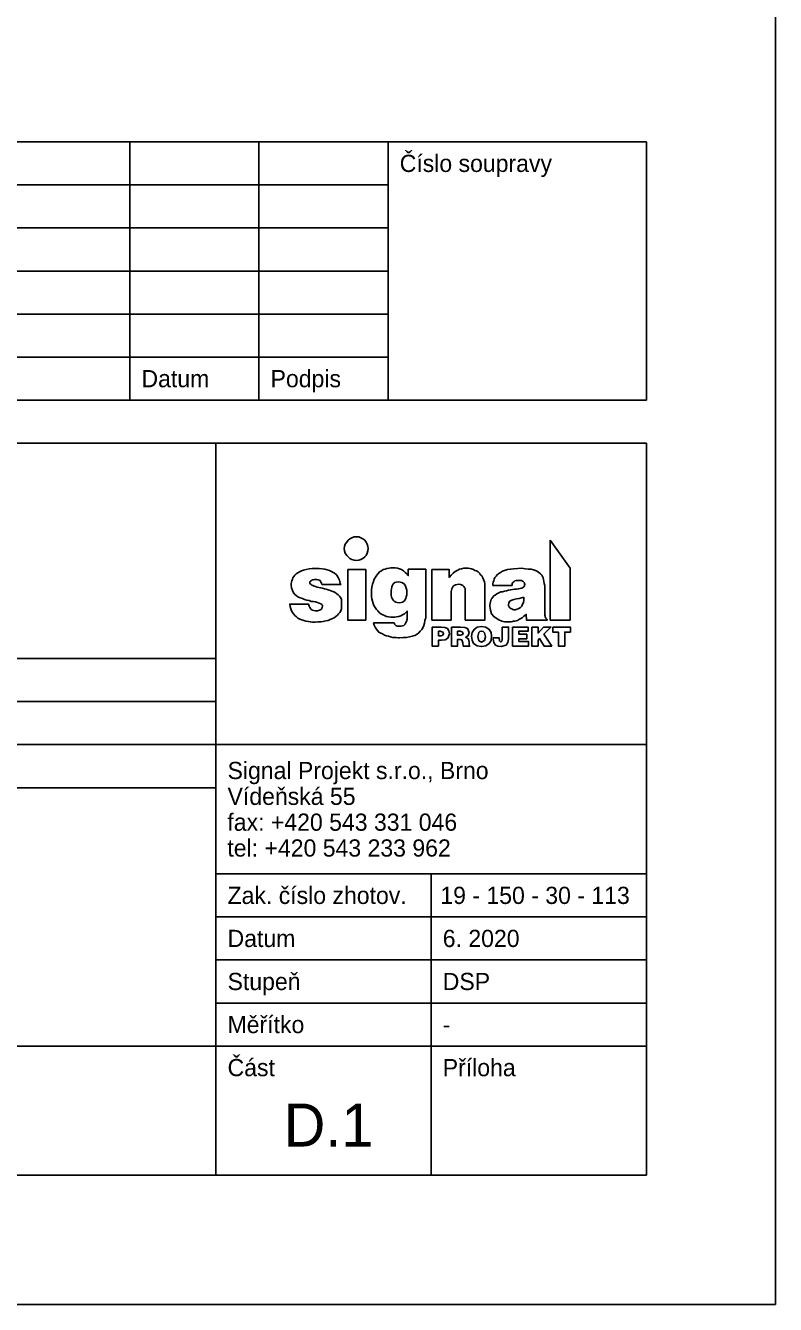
# Model space of a CAD drawing. Extents: x -790471 to -790261, y -986448 to -986151.
# Drawn here: x -790347.7 to -790260.6, y -986447.6 to -986299.1 of the extents above; entities that cross this region are included whole.
import ezdxf

# ---------------------------------------------------------------- set-up
doc = ezdxf.new("R2010")
doc.units = 0
for name, color, linetype in [('Info o rozpiskách', 7, 'Continuous'), ('popis', 7, 'Continuous'), ('Ramečky', 7, 'Continuous'), ('Rámečky-tisk', 7, 'Continuous'), ('Text', 7, 'Continuous'), ('Text barevný', 7, 'Continuous')]:
    doc.layers.add(name, color=color, linetype=linetype)

msp = doc.modelspace()

# ---------------------------------------------------------------- linework, layer by layer
at = {"layer": 'Info o rozpiskách'}
for points in [[(-790309.25, -986358.46), (-790308.98, -986358.47), (-790308.76, -986358.57), (-790308.54, -986358.7), (-790308.29, -986358.87), (-790308.15, -986359.07), (-790308.03, -986359.31), (-790307.94, -986359.58), (-790307.92, -986359.84), (-790307.94, -986360.1), (-790308.03, -986360.38), (-790308.15, -986360.62), (-790308.29, -986360.79), (-790308.54, -986360.99), (-790308.76, -986361.09), (-790308.98, -986361.18), (-790309.25, -986361.2), (-790309.54, -986361.18), (-790309.79, -986361.09), (-790310.05, -986360.99), (-790310.23, -986360.79), (-790310.4, -986360.62), (-790310.57, -986360.38), (-790310.65, -986360.1), (-790310.7, -986359.84), (-790310.65, -986359.58), (-790310.57, -986359.31), (-790310.4, -986359.07), (-790310.23, -986358.87), (-790310.05, -986358.7), (-790309.79, -986358.57), (-790309.54, -986358.47), (-790309.25, -986358.46)], [(-790300.48, -986368.94), (-790299.41, -986368.94), (-790299, -986368.98), (-790298.7, -986369.13), (-790298.52, -986369.37), (-790298.46, -986369.72), (-790298.65, -986370.25), (-790298.95, -986370.42), (-790299.38, -986370.47), (-790299.75, -986370.47), (-790299.75, -986371.16), (-790300.48, -986371.16), (-790300.48, -986368.94)], [(-790299.75, -986369.44), (-790299.75, -986369.95), (-790299.43, -986369.95), (-790299.25, -986369.89), (-790299.15, -986369.69), (-790299.23, -986369.52), (-790299.54, -986369.44), (-790299.75, -986369.44)], [(-790298.24, -986368.94), (-790297.16, -986368.94), (-790296.67, -986368.98), (-790296.35, -986369.13), (-790296.19, -986369.58), (-790296.3, -986369.93), (-790296.56, -986370.12), (-790296.24, -986370.34), (-790296.19, -986370.71), (-790296.19, -986370.88), (-790296.17, -986371.05), (-790296.11, -986371.11), (-790296.11, -986371.16), (-790296.86, -986371.16), (-790296.9, -986370.77), (-790297.03, -986370.42), (-790297.18, -986370.4), (-790297.4, -986370.38), (-790297.51, -986370.38), (-790297.51, -986371.16), (-790298.24, -986371.16), (-790298.24, -986368.94)], [(-790297.51, -986369.44), (-790297.51, -986369.89), (-790297.19, -986369.89), (-790296.93, -986369.82), (-790296.88, -986369.69), (-790296.95, -986369.52), (-790297.16, -986369.44), (-790297.51, -986369.44)], [(-790294.73, -986368.89), (-790294.23, -986368.96), (-790293.84, -986369.22), (-790293.63, -986369.59), (-790293.56, -986370.02), (-790293.63, -986370.49), (-790293.85, -986370.86), (-790294.23, -986371.12), (-790294.73, -986371.22), (-790295.25, -986371.12), (-790295.65, -986370.84), (-790295.83, -986370.47), (-790295.91, -986370.02), (-790295.83, -986369.58), (-790295.61, -986369.22), (-790295.23, -986368.96), (-790294.73, -986368.89)], [(-790294.73, -986369.43), (-790294.92, -986369.46), (-790295.05, -986369.58), (-790295.16, -986370.04), (-790295.05, -986370.53), (-790294.73, -986370.68), (-790294.38, -986370.49), (-790294.28, -986370.08), (-790294.4, -986369.61), (-790294.53, -986369.46), (-790294.73, -986369.43)], [(-790292.33, -986368.94), (-790291.6, -986368.94), (-790291.6, -986370.32), (-790291.67, -986370.75), (-790291.88, -986371.05), (-790292.46, -986371.22), (-790292.83, -986371.18), (-790293.11, -986371.03), (-790293.29, -986370.75), (-790293.37, -986370.36), (-790293.35, -986370.19), (-790292.7, -986370.19), (-790292.66, -986370.56), (-790292.51, -986370.68), (-790292.38, -986370.6), (-790292.33, -986370.42), (-790292.33, -986368.94)], [(-790291.13, -986368.94), (-790289.32, -986368.94), (-790289.32, -986369.44), (-790290.4, -986369.44), (-790290.4, -986369.78), (-790289.49, -986369.78), (-790289.49, -986370.3), (-790290.4, -986370.3), (-790290.4, -986370.64), (-790289.27, -986370.64), (-790289.27, -986371.16), (-790291.13, -986371.16), (-790291.13, -986368.94)], [(-790288.91, -986368.94), (-790288.16, -986368.94), (-790288.16, -986369.65), (-790287.53, -986368.94), (-790286.67, -986368.94), (-790287.49, -986369.78), (-790286.58, -986371.16), (-790287.46, -986371.16), (-790288, -986370.28), (-790288.16, -986370.45), (-790288.16, -986371.16), (-790288.91, -986371.16), (-790288.91, -986368.94)], [(-790286.47, -986368.94), (-790284.41, -986368.94), (-790284.41, -986369.52), (-790285.07, -986369.52), (-790285.07, -986371.16), (-790285.8, -986371.16), (-790285.8, -986369.52), (-790286.47, -986369.52), (-790286.47, -986368.94)]]:
    msp.add_lwpolyline(points, dxfattribs=at)
at = {"layer": 'popis'}
for points in [[(-790286.77, -986358.87), (-790286.77, -986368.14), (-790284.45, -986368.14), (-790284.45, -986362.11), (-790286.77, -986358.87)], [(-790313.29, -986364.02), (-790311.09, -986364.02), (-790311.15, -986363.83), (-790311.19, -986363.66), (-790311.24, -986363.49), (-790311.32, -986363.33), (-790311.41, -986363.18), (-790311.52, -986363.01), (-790311.63, -986362.86), (-790311.8, -986362.69), (-790311.97, -986362.6), (-790312.17, -986362.49), (-790312.4, -986362.39), (-790312.66, -986362.3), (-790312.94, -986362.24), (-790313.26, -986362.19), (-790313.61, -986362.15), (-790314, -986362.13), (-790314.4, -986362.15), (-790314.77, -986362.19), (-790315.09, -986362.26), (-790315.4, -986362.32), (-790315.66, -986362.41), (-790315.89, -986362.52), (-790316.07, -986362.65), (-790316.26, -986362.78), (-790316.43, -986362.93), (-790316.54, -986363.08), (-790316.65, -986363.23), (-790316.71, -986363.4), (-790316.78, -986363.59), (-790316.82, -986363.75), (-790316.86, -986363.89), (-790316.86, -986364.09), (-790316.8, -986364.39), (-790316.71, -986364.69), (-790316.62, -986364.91), (-790316.43, -986365.15), (-790316.26, -986365.28), (-790316.06, -986365.45), (-790315.81, -986365.56), (-790315.55, -986365.64), (-790315.29, -986365.73), (-790315.03, -986365.81), (-790314.77, -986365.88), (-790314.51, -986365.96), (-790314.25, -986365.99), (-790314.02, -986366.03), (-790313.8, -986366.09), (-790313.59, -986366.18), (-790313.39, -986366.25), (-790313.29, -986366.33), (-790313.22, -986366.42), (-790313.2, -986366.52), (-790313.24, -986366.68), (-790313.29, -986366.76), (-790313.33, -986366.85), (-790313.44, -986366.93), (-790313.57, -986367), (-790313.67, -986367.04), (-790313.8, -986367.08), (-790313.93, -986367.08), (-790314.06, -986367.08), (-790314.21, -986367.04), (-790314.38, -986366.98), (-790314.47, -986366.93), (-790314.6, -986366.8), (-790314.69, -986366.68), (-790314.77, -986366.5), (-790314.82, -986366.27), (-790317.01, -986366.27), (-790316.97, -986366.57), (-790316.9, -986366.83), (-790316.8, -986367.06), (-790316.69, -986367.24), (-790316.56, -986367.43), (-790316.41, -986367.6), (-790316.24, -986367.77), (-790316.06, -986367.9), (-790315.83, -986368.01), (-790315.61, -986368.12), (-790315.38, -986368.2), (-790315.14, -986368.27), (-790314.86, -986368.29), (-790314.62, -986368.34), (-790314.38, -986368.36), (-790314.06, -986368.36), (-790313.74, -986368.34), (-790313.43, -986368.34), (-790313.13, -986368.29), (-790312.83, -986368.23), (-790312.55, -986368.18), (-790312.31, -986368.08), (-790312.06, -986367.95), (-790311.86, -986367.86), (-790311.65, -986367.73), (-790311.47, -986367.56), (-790311.34, -986367.41), (-790311.2, -986367.24), (-790311.09, -986367.06), (-790311.02, -986366.83), (-790311, -986366.61), (-790311, -986366.39), (-790311, -986366.33), (-790311, -986366.27), (-790311, -986366.22), (-790311, -986366.16), (-790311, -986366.09), (-790311, -986366.03), (-790311, -986365.99), (-790311, -986365.96), (-790311.02, -986365.71), (-790311.11, -986365.53), (-790311.24, -986365.34), (-790311.39, -986365.21), (-790311.54, -986365.08), (-790311.73, -986364.93), (-790311.9, -986364.84), (-790312.12, -986364.76), (-790312.32, -986364.69), (-790312.55, -986364.61), (-790312.77, -986364.54), (-790312.98, -986364.5), (-790313.22, -986364.44), (-790313.43, -986364.39), (-790313.65, -986364.35), (-790313.84, -986364.3), (-790314.02, -986364.22), (-790314.19, -986364.18), (-790314.32, -986364.11), (-790314.45, -986364.07), (-790314.53, -986364.02), (-790314.64, -986363.94), (-790314.67, -986363.89), (-790314.67, -986363.81), (-790314.67, -986363.74), (-790314.64, -986363.66), (-790314.56, -986363.59), (-790314.49, -986363.55), (-790314.41, -986363.47), (-790314.28, -986363.47), (-790314.13, -986363.44), (-790314, -986363.44), (-790313.85, -986363.44), (-790313.72, -986363.47), (-790313.61, -986363.49), (-790313.5, -986363.55), (-790313.43, -986363.64), (-790313.39, -986363.74), (-790313.31, -986363.85), (-790313.29, -986364.02)], [(-790303.24, -986362.24), (-790303.24, -986362.97), (-790303.41, -986362.77), (-790303.59, -986362.6), (-790303.8, -986362.43), (-790304.04, -986362.28), (-790304.28, -986362.17), (-790304.51, -986362.11), (-790304.75, -986362.08), (-790305.03, -986362.06), (-790305.29, -986362.08), (-790305.48, -986362.09), (-790305.74, -986362.13), (-790305.93, -986362.23), (-790306.15, -986362.28), (-790306.35, -986362.43), (-790306.58, -986362.54), (-790306.76, -986362.73), (-790306.91, -986362.92), (-790307.06, -986363.16), (-790307.19, -986363.4), (-790307.29, -986363.64), (-790307.4, -986363.96), (-790307.47, -986364.3), (-790307.51, -986364.67), (-790307.51, -986365.06), (-790307.51, -986365.38), (-790307.47, -986365.66), (-790307.4, -986365.92), (-790307.32, -986366.2), (-790307.23, -986366.44), (-790307.1, -986366.68), (-790306.93, -986366.89), (-790306.78, -986367.08), (-790306.62, -986367.24), (-790306.45, -986367.39), (-790306.22, -986367.52), (-790306, -986367.62), (-790305.78, -986367.71), (-790305.53, -986367.77), (-790305.29, -986367.8), (-790305.03, -986367.8), (-790304.81, -986367.8), (-790304.6, -986367.77), (-790304.34, -986367.73), (-790304.12, -986367.64), (-790303.91, -986367.54), (-790303.7, -986367.41), (-790303.56, -986367.28), (-790303.39, -986367.09), (-790303.39, -986367.64), (-790303.39, -986368.03), (-790303.46, -986368.29), (-790303.56, -986368.49), (-790303.63, -986368.64), (-790303.76, -986368.75), (-790303.91, -986368.79), (-790304.08, -986368.85), (-790304.26, -986368.85), (-790304.36, -986368.85), (-790304.49, -986368.83), (-790304.6, -986368.79), (-790304.69, -986368.75), (-790304.75, -986368.68), (-790304.84, -986368.61), (-790304.86, -986368.53), (-790304.9, -986368.44), (-790307.27, -986368.44), (-790307.21, -986368.74), (-790307.1, -986368.94), (-790306.97, -986369.17), (-790306.84, -986369.33), (-790306.67, -986369.54), (-790306.45, -986369.65), (-790306.24, -986369.74), (-790306, -986369.89), (-790305.78, -986369.97), (-790305.53, -986370.02), (-790305.31, -986370.08), (-790305.05, -986370.14), (-790304.84, -986370.15), (-790304.66, -986370.17), (-790304.43, -986370.19), (-790304.26, -986370.19), (-790303.85, -986370.17), (-790303.46, -986370.14), (-790303.09, -986370.08), (-790302.79, -986370.01), (-790302.49, -986369.91), (-790302.23, -986369.78), (-790302.03, -986369.63), (-790301.86, -986369.44), (-790301.69, -986369.24), (-790301.56, -986369.02), (-790301.45, -986368.77), (-790301.35, -986368.49), (-790301.32, -986368.2), (-790301.22, -986367.86), (-790301.22, -986367.51), (-790301.22, -986367.09), (-790301.22, -986362.24), (-790303.24, -986362.24)], [(-790300.5, -986362.26), (-790300.5, -986368.14), (-790298.26, -986368.14), (-790298.26, -986365.14), (-790298.26, -986364.82), (-790298.2, -986364.52), (-790298.11, -986364.35), (-790298.03, -986364.2), (-790297.9, -986364.11), (-790297.75, -986364.03), (-790297.57, -986364.02), (-790297.38, -986363.98), (-790297.19, -986364.02), (-790297.06, -986364.05), (-790296.9, -986364.11), (-790296.8, -986364.22), (-790296.73, -986364.35), (-790296.65, -986364.52), (-790296.62, -986364.78), (-790296.62, -986365.04), (-790296.62, -986368.14), (-790294.34, -986368.14), (-790294.34, -986364.59), (-790294.34, -986364.28), (-790294.36, -986363.98), (-790294.41, -986363.7), (-790294.51, -986363.44), (-790294.6, -986363.21), (-790294.71, -986363.01), (-790294.88, -986362.84), (-790294.99, -986362.67), (-790295.14, -986362.54), (-790295.31, -986362.41), (-790295.5, -986362.36), (-790295.68, -986362.26), (-790295.91, -986362.19), (-790296.09, -986362.15), (-790296.28, -986362.11), (-790296.5, -986362.11), (-790296.78, -986362.11), (-790297.06, -986362.19), (-790297.31, -986362.23), (-790297.57, -986362.36), (-790297.81, -986362.49), (-790298.05, -986362.67), (-790298.26, -986362.92), (-790298.5, -986363.18), (-790298.5, -986362.26), (-790300.5, -986362.26)], [(-790293.41, -986364.11), (-790291.19, -986364.11), (-790291.17, -986363.94), (-790291.13, -986363.81), (-790291.06, -986363.72), (-790290.96, -986363.64), (-790290.85, -986363.57), (-790290.7, -986363.53), (-790290.57, -986363.53), (-790290.42, -986363.53), (-790290.25, -986363.53), (-790290.09, -986363.55), (-790289.96, -986363.62), (-790289.88, -986363.66), (-790289.81, -986363.74), (-790289.73, -986363.81), (-790289.73, -986363.9), (-790289.69, -986364), (-790289.73, -986364.09), (-790289.75, -986364.2), (-790289.84, -986364.28), (-790289.94, -986364.35), (-790290.07, -986364.43), (-790290.25, -986364.46), (-790290.46, -986364.5), (-790290.66, -986364.54), (-790290.89, -986364.56), (-790291.13, -986364.59), (-790291.36, -986364.63), (-790291.6, -986364.67), (-790291.84, -986364.73), (-790292.08, -986364.76), (-790292.29, -986364.84), (-790292.51, -986364.87), (-790292.74, -986364.97), (-790292.96, -986365.08), (-790293.15, -986365.23), (-790293.31, -986365.32), (-790293.44, -986365.47), (-790293.54, -986365.62), (-790293.61, -986365.71), (-790293.67, -986365.88), (-790293.7, -986366.03), (-790293.74, -986366.2), (-790293.76, -986366.35), (-790293.76, -986366.52), (-790293.7, -986367), (-790293.56, -986367.39), (-790293.31, -986367.73), (-790293.05, -986367.93), (-790292.74, -986368.12), (-790292.38, -986368.25), (-790292.06, -986368.33), (-790291.73, -986368.34), (-790291.58, -986368.34), (-790291.45, -986368.33), (-790291.3, -986368.33), (-790291.13, -986368.29), (-790291.02, -986368.27), (-790290.85, -986368.25), (-790290.7, -986368.21), (-790290.57, -986368.18), (-790290.44, -986368.1), (-790290.31, -986368.03), (-790290.18, -986367.97), (-790290.03, -986367.88), (-790289.92, -986367.78), (-790289.81, -986367.67), (-790289.66, -986367.56), (-790289.55, -986367.47), (-790289.51, -986368.16), (-790287.12, -986368.16), (-790287.12, -986368.06), (-790287.25, -986367.93), (-790287.31, -986367.84), (-790287.36, -986367.75), (-790287.36, -986367.67), (-790287.4, -986367.56), (-790287.4, -986367.49), (-790287.4, -986367.37), (-790287.4, -986367.23), (-790287.4, -986364.35), (-790287.4, -986364.11), (-790287.46, -986363.87), (-790287.49, -986363.64), (-790287.53, -986363.42), (-790287.59, -986363.23), (-790287.64, -986363.08), (-790287.74, -986362.92), (-790287.9, -986362.75), (-790288.07, -986362.62), (-790288.24, -986362.51), (-790288.46, -986362.39), (-790288.71, -986362.3), (-790288.97, -986362.24), (-790289.3, -986362.21), (-790289.66, -986362.17), (-790290.07, -986362.11), (-790290.53, -986362.13), (-790291.02, -986362.17), (-790291.37, -986362.23), (-790291.73, -986362.28), (-790292.05, -986362.37), (-790292.29, -986362.47), (-790292.53, -986362.6), (-790292.74, -986362.73), (-790292.92, -986362.88), (-790293.05, -986363.03), (-790293.2, -986363.2), (-790293.28, -986363.38), (-790293.31, -986363.53), (-790293.37, -986363.72), (-790293.41, -986363.9), (-790293.41, -986364.11)], [(-790310.27, -986362.26), (-790310.27, -986368.14), (-790308.18, -986368.14), (-790308.18, -986362.26), (-790310.27, -986362.26)], [(-790304.39, -986363.7), (-790304.19, -986363.74), (-790303.98, -986363.79), (-790303.8, -986363.89), (-790303.65, -986364.02), (-790303.56, -986364.2), (-790303.48, -986364.41), (-790303.41, -986364.67), (-790303.41, -986364.95), (-790303.41, -986365.19), (-790303.48, -986365.42), (-790303.54, -986365.64), (-790303.63, -986365.81), (-790303.74, -986365.92), (-790303.91, -986366.05), (-790304.08, -986366.11), (-790304.3, -986366.12), (-790304.53, -986366.11), (-790304.71, -986366.05), (-790304.9, -986365.92), (-790305.01, -986365.83), (-790305.1, -986365.64), (-790305.2, -986365.47), (-790305.23, -986365.25), (-790305.25, -986365.01), (-790305.23, -986364.74), (-790305.2, -986364.5), (-790305.16, -986364.28), (-790305.09, -986364.07), (-790304.99, -986363.94), (-790304.82, -986363.79), (-790304.64, -986363.74), (-790304.39, -986363.7)], [(-790289.81, -986365.47), (-790289.81, -986365.49), (-790289.81, -986365.55), (-790289.81, -986365.58), (-790289.84, -986365.84), (-790289.86, -986366.11), (-790289.96, -986366.29), (-790290.07, -986366.52), (-790290.22, -986366.68), (-790290.4, -986366.78), (-790290.61, -986366.87), (-790290.81, -986366.93), (-790290.98, -986366.93), (-790291.09, -986366.89), (-790291.21, -986366.83), (-790291.32, -986366.78), (-790291.43, -986366.7), (-790291.52, -986366.61), (-790291.6, -986366.52), (-790291.62, -986366.37), (-790291.58, -986366.12), (-790291.45, -986365.94), (-790291.22, -986365.83), (-790290.98, -986365.75), (-790290.66, -986365.68), (-790290.38, -986365.64), (-790290.09, -986365.55), (-790289.81, -986365.47)]]:
    msp.add_lwpolyline(points, dxfattribs=at)
at = {"layer": 'Ramečky'}
for p, q in [((-790275.59, -986312.6), (-790455.59, -986312.6)), ((-790335.59, -986312.6), (-790335.59, -986342.6)), ((-790320.59, -986312.6), (-790320.59, -986342.6)), ((-790305.59, -986312.6), (-790305.59, -986342.6)), ((-790275.59, -986312.6), (-790275.59, -986342.6)), ((-790305.59, -986317.6), (-790455.59, -986317.6)), ((-790305.59, -986322.6), (-790455.59, -986322.6)), ((-790305.59, -986327.6), (-790455.59, -986327.6)), ((-790305.59, -986332.6), (-790455.59, -986332.6)), ((-790305.59, -986337.6), (-790455.59, -986337.6)), ((-790275.59, -986342.6), (-790455.59, -986342.6)), ((-790275.59, -986347.6), (-790455.59, -986347.6)), ((-790325.59, -986432.6), (-790325.59, -986347.6)), ((-790275.59, -986432.6), (-790275.59, -986347.6)), ((-790455.59, -986372.6), (-790325.59, -986372.6)), ((-790455.59, -986377.6), (-790325.59, -986377.6)), ((-790455.59, -986382.6), (-790325.59, -986382.6)), ((-790455.59, -986387.6), (-790325.59, -986387.6)), ((-790325.59, -986397.6), (-790275.59, -986397.6)), ((-790325.59, -986402.6), (-790275.59, -986402.6)), ((-790325.59, -986407.6), (-790275.59, -986407.6)), ((-790325.59, -986412.6), (-790275.59, -986412.6)), ((-790455.59, -986417.6), (-790275.59, -986417.6)), ((-790455.59, -986432.6), (-790275.59, -986432.6))]:
    msp.add_line(p, q, dxfattribs=at)
for points in [[(-790325.59, -986382.6), (-790275.59, -986382.6)], [(-790300.59, -986397.6), (-790300.59, -986432.6)]]:
    msp.add_lwpolyline(points, dxfattribs=at)
at = {"layer": 'Rámečky-tisk'}
msp.add_lwpolyline([(-790470.59, -986447.6), (-790260.59, -986447.6), (-790260.59, -986150.6)], dxfattribs=at)

# ---------------------------------------------------------------- texts
at = {"layer": 'Text'}
for s, p in [('Číslo soupravy', (-790304.24, -986316.1)), ('Datum', (-790334.24, -986341.1)), ('Podpis', (-790319.24, -986341.1)), ('Signal Projekt s.r.o., Brno', (-790324.24, -986386.6)), ('Vídeňská 55', (-790324.24, -986389.6)), ('fax: +420 543 331 046', (-790324.26, -986392.6)), ('tel: +420 543 233 962', (-790324.26, -986395.6)), ('Zak. číslo zhotov.', (-790324.24, -986401.1)), ('19 - 150 - 30 - 113', (-790299.52, -986401.1)), ('Datum', (-790324.24, -986406.1)), ('6. 2020', (-790299.24, -986406.1)), ('Stupeň', (-790324.24, -986411.1)), ('DSP', (-790299.24, -986411.1)), ('Měřítko', (-790324.24, -986416.1)), ('-', (-790299.24, -986416.1)), ('Část', (-790324.24, -986421.1)), ('Příloha', (-790299.24, -986421.1))]:
    msp.add_text(s, height=2, dxfattribs=at).set_placement(p)
at = {"layer": 'Text barevný'}
msp.add_text('D.1', height=5, dxfattribs=at).set_placement((-790317.71, -986429.27))

doc.saveas('drawing.dxf')
